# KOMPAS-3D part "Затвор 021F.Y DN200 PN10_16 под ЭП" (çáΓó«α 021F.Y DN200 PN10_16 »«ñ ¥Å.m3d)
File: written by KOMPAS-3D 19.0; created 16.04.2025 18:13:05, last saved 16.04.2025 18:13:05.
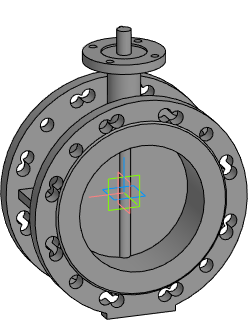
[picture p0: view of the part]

Document properties: Автор: Евгений; Полное имя файла: E:\Dendor Работа Сачек\3D для проекитирвщиков\1.6 Тип 021F.Y Затвор дисковый поворотный фланцевый\stp_Тип 021F.Y Затвор  DN40 PN10_16 под ЭП\Затвор 021F.Y DN200 PN10_16 под ЭП.m3d

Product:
- Part/product: Затвор 021F.Y DN200 PN10_16 под ЭП

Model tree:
1. Операция без истории:1  (labels: Затвор 021F.Y DN200 PN10_16 под ЭП)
